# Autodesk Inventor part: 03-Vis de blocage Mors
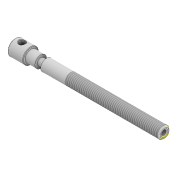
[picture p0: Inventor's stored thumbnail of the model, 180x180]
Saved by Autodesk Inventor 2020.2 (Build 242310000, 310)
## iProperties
Created: 2022-02
Part Number: 03-Vis de blocage Mors
Material: Acier, alliage
Document SubType Name: Modeling
Designer: Philippe
Density: 7.73 g/cm^3
Appearance: Semi-poli
Author: Philippe
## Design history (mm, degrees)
derived "Base-Etau.ipt"
sketch "Esquisse1"
  geometry: A1 r 5 centre (0, 0) between (-5, 0) and (0, 5); 1 further point
  constraints: 2 point on circle, 1 centre point, 1 coincident
  dimensions: "d1" = 5 radius of A1
feature "SrfExtrusion1" sketch "Esquisse1" dims "d2" = 97, "d3" = 0
sketch "Esquisse2"
  geometry: A1 r 3 centre (0, 0) between (-3, 0) and (0, 3); 1 further point
  constraints: 2 point on circle, 1 centre point, 1 coincident
  dimensions: "d4" = 3 radius of A1
feature "SrfExtrusion2" sketch "Esquisse2" dims "d5" = 13, "d6" = 0
feature "03-Vis de blocage Mors::Base-Etau.ipt" dims "d0" = 10
tag "FonctionRepérage1"
body "Srf1"
body "Srf2"
node "Solide1"
